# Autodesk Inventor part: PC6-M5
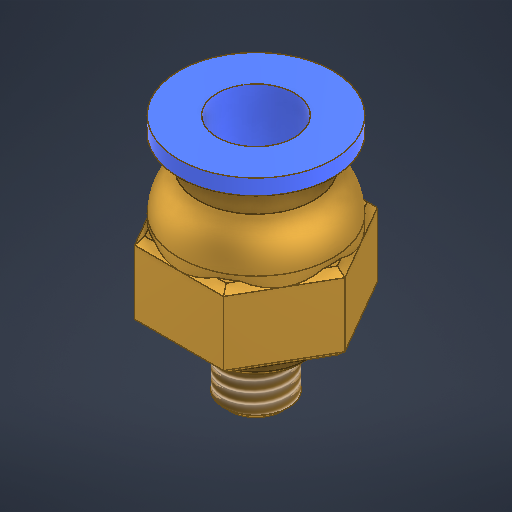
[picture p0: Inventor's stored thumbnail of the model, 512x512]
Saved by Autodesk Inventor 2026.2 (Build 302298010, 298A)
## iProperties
Created: 2026-05
Part Number: PC6-M5
Material: 황동, 연질 노란색
Document SubType Name: Modeling
Designer: work
Density: 8.47 g/cm^3
Appearance: 황동 - 새틴
Author: work
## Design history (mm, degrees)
sketch "스케치1"
  geometry: L1 (6.928, 0)-(3.464, -6); L2 (3.464, -6)-(-3.464, -6); L3 (-3.464, -6)-(-6.928, 0); L4 (-6.928, 0)-(-3.464, 6); L5 (-3.464, 6)-(3.464, 6); L6 (3.464, 6)-(6.928, 0); L7 (6.928, 0)-(0, 0); L8 (0, 0)-(5.196, -3); L9 (0, 0)-(-5.196, 3); 1 further point
  constraints: 18 end point, 2 midpoint, 1 coincident, 1 horizontal, 13 other
  dimensions: "d0" = 12 distance between parallel lines of L4 L1
extrude "돌출1" new body sketch "스케치1" distance "d1" = 6; taper "d2" = 0 deg
sketch "스케치2"
  geometry: C1 r 4 at (0, 0); 1 further point
  constraints: 1 centre point, 1 coincident
  dimensions: "d3" = 8 diameter of C1
extrude "돌출2" join sketch "스케치2" distance "d4" = 2; taper "d5" = 0 deg
sketch "스케치3"
  geometry: C1 r 2.5 at (0, 0); 1 further point
  constraints: 1 centre point, 1 coincident
  dimensions: "d6" = 5 diameter of C1
extrude "돌출3" join sketch "스케치3" distance "d7" = 4; taper "d8" = 0 deg
feature "스레드1" dims "d9" = 4, "d10" = 0
sketch "스케치4"
  geometry: L1 (3.464, 6)-(-3.464, 6) reference; L2 (0, 6)-(0, 16.933); L3 (0, 6)-(6, 6); L4 (6.928, 6)-(3.464, 6) reference; L5 (0, 11)-(4.5, 11); L6 (4.5, 11)-(4.5, 9.5); L7 (6, 6.378)-(6, 6); L8 (3, 11)-(3, 13); L9 (3, 13)-(6, 13); L10 (6, 13)-(6, 11.8); L11 (6, 11.8)-(4, 11.8); L12 (4, 11.8)-(4, 11); L13 (6.928, 0)-(3.464, 0) reference; A1 r 4 centre (2, 6.378) between (6, 6.378) and (4.5, 9.5); 3 further points
  constraints: 20 end point, 5 perpendicular, 4 point on line, 3 vertical, 2 midpoint, 2 point on circle, 1 centre point, 1 horizontal, 1 tangent
  dimensions: "d11" = 6 distance of L2.start L3.end; "d12" = 4.5 distance of L5.start L5.end; "d13" = 1.5 distance of L5.end L6.end; "d14" = 4 radius of A1; "d15" = 3.5 distance from line of L3 L6.end; "d16" = 1.2 distance of L9.end L10.end; "d17" = 6 diameter of L8 L2; "d19" = 8 diameter of L12 L2; "d21" = 7 distance between parallel lines of L4 L9; "d22" = 12 diameter of L10 L2
revolve "회전1" sketch "스케치4" stored, may be unused: angle "d23" = 90 deg
sketch "스케치5"
  geometry: C1 r 2.5 at (0, 0) reference; C2 r 3 at (0, 0); 1 further point
  constraints: 1 centre point, 1 coincident
  dimensions: "d24" = 6 diameter of C2
extrude "돌출4" cut sketch "스케치5" distance "d25" = 10; taper "d26" = 0 deg
sketch "스케치6"
  geometry: C1 r 1 at (0, 0); 1 further point
  constraints: 1 centre point, 1 coincident
  dimensions: "d27" = 2 diameter of C1
extrude "돌출5" cut sketch "스케치6" extent not by distance; stored distance "d28" = 0; taper "d29" = 0 deg
chamfer "모따기1" distance "d30" = 0.5; stored, may be unused: second distance "d31" = 2, angle "d32" = 45 deg
chamfer "모따기2" distance "d33" = 0.5; stored, may be unused: second distance "d34" = 2, angle "d35" = 45 deg
node "솔리드1"
feature "A9D066F2-1C7D-4E18-AEED-F7BC21143FA4" dims "d9" = 4, "d10" = 0
